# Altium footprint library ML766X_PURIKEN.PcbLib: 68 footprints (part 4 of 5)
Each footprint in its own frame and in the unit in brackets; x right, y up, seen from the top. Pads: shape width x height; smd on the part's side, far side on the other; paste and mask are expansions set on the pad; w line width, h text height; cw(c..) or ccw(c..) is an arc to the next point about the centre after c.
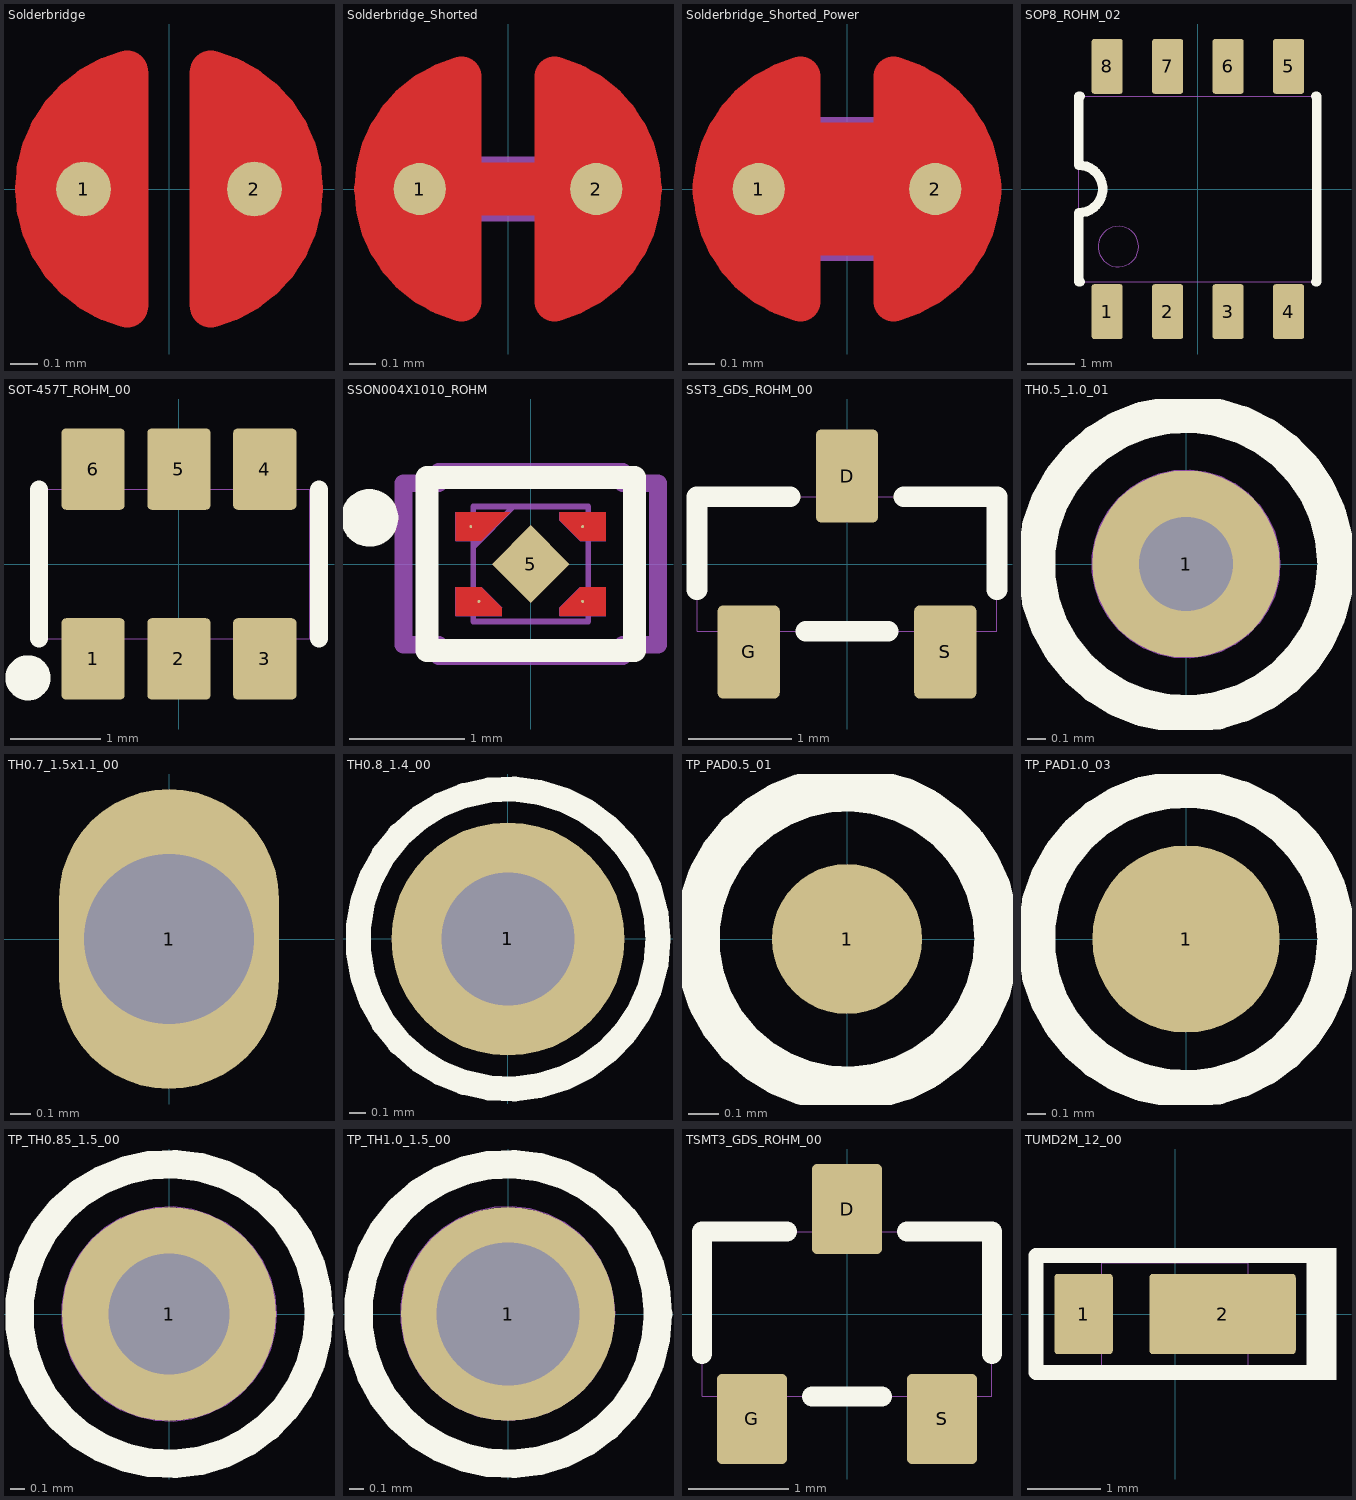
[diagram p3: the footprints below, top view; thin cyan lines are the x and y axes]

## Solderbridge [mm]
height 0.55
pads (2):
  round 0.2 smd paste-10: 1(-0.312,0) 2(0.312,0)
Top Layer:
  region: -0.077,-0.432 -0.152,-0.505 -0.271,-0.467 -0.335,-0.424 -0.409,-0.351 -0.462,-0.292 -0.521,-0.193 -0.549,-0.099 -0.544,0.122 -0.518,0.193 -0.434,0.33 -0.351,0.411 -0.259,0.469 -0.157,0.5 -0.107,0.483 -0.077,0.43
  region: 0.077,0.432 0.152,0.505 0.271,0.467 0.335,0.424 0.409,0.351 0.462,0.292 0.521,0.193 0.549,0.099 0.544,-0.122 0.518,-0.193 0.434,-0.33 0.351,-0.411 0.259,-0.469 0.157,-0.5 0.107,-0.483 0.077,-0.43
  lines w0.152: -0.153,-0.431 cw(c-0.042,0) -0.153,0.431 ; 0.153,-0.431 ccw(c0.042,0) 0.153,0.431
Top Solder:
  circle w0.61: c-0.003,0 r0.279
Top Component Outline:
  lines w0.05: -0.123,-0.459 cw(c-0.042,0) -0.123,0.459 -0.123,-0.459 ; 0.123,-0.459 ccw(c0.042,0) 0.123,0.459 0.123,-0.459

## Solderbridge_Shorted [mm]
height 0.55
pads (2):
  round 0.2 smd paste-10: 1(-0.338,0) 2(0.338,0)
Top Layer:
  region: 0.102,0.432 0.178,0.505 0.296,0.467 0.361,0.424 0.434,0.351 0.488,0.292 0.546,0.193 0.574,0.099 0.569,-0.122 0.544,-0.193 0.46,-0.33 0.376,-0.411 0.284,-0.469 0.183,-0.5 0.132,-0.483 0.102,-0.43
  region: -0.102,-0.432 -0.178,-0.505 -0.296,-0.467 -0.361,-0.424 -0.434,-0.351 -0.488,-0.292 -0.546,-0.193 -0.574,-0.099 -0.569,0.122 -0.544,0.193 -0.46,0.33 -0.376,0.411 -0.284,0.469 -0.183,0.5 -0.132,0.483 -0.102,0.43
  lines w0.152: -0.178,-0.431 cw(c-0.068,0) -0.178,0.431 ; 0.178,-0.431 ccw(c0.068,0) 0.178,0.431
  lines w0.203: -0.338,0 0.338,0
Top Solder:
  circle w0.61: c0.028,0 r0.279
  circle w0.61: c-0.028,0 r0.279
Top Component Outline:
  lines w0.05: -0.148,-0.459 cw(c-0.067,0) -0.148,0.459 -0.148,0.1 0.148,0.1 0.148,0.459 cw(c0.067,0) 0.148,-0.459 0.148,-0.1 -0.148,-0.1 -0.148,-0.459

## Solderbridge_Shorted_Power [mm]
height 2.54
pads (2):
  round 0.2 smd paste-10: 1(-0.338,0) 2(0.338,0)
Top Layer:
  region: -0.102,-0.432 -0.178,-0.505 -0.296,-0.467 -0.361,-0.424 -0.434,-0.351 -0.488,-0.292 -0.546,-0.193 -0.574,-0.099 -0.569,0.122 -0.544,0.193 -0.46,0.33 -0.376,0.411 -0.284,0.469 -0.183,0.5 -0.132,0.483 -0.102,0.43
  region: 0.102,0.432 0.178,0.505 0.296,0.467 0.361,0.424 0.434,0.351 0.488,0.292 0.546,0.193 0.574,0.099 0.569,-0.122 0.544,-0.193 0.46,-0.33 0.376,-0.411 0.284,-0.469 0.183,-0.5 0.132,-0.483 0.102,-0.43
  lines w0.152: -0.178,-0.431 cw(c-0.068,0) -0.178,0.431 ; 0.178,-0.431 ccw(c0.068,0) 0.178,0.431
  lines w0.508: -0.338,0 0.338,0
Top Solder:
  circle w0.61: c0.028,0 r0.279
  circle w0.61: c-0.028,0 r0.279
Top Component Outline:
  lines w0.05: 0.148,-0.25 0.148,-0.459 ccw(c0.067,0) 0.148,0.459 0.148,0.25 -0.148,0.25 -0.148,0.459 ccw(c-0.067,0) -0.148,-0.459 -0.148,-0.25 0.175,-0.25

## SOP8_ROHM_02 [mm]
height 1.75
pads (8):
  rrect15% 0.65x1.15 smd: 1(-1.905,-2.575) 2(-0.635,-2.575) 3(0.635,-2.575) 4(1.905,-2.575) 5(1.905,2.575) 6(0.635,2.575) 7(-0.635,2.575) 8(-1.905,2.575)
Top Overlay:
  lines w0.2: -2.475,-1.95 -2.5,-1.95 -2.5,-0.5 ccw(c-2.5,0) -2.5,0.5 -2.5,1.95 -2.475,1.95 ; 2.475,-1.95 2.5,-1.95 2.5,1.95 2.475,1.95
Top Component Outline:
  circle w0.01: c-1.67,-1.21 r0.426
  lines w0.01: -2.5,-1.95 -2.5,1.95 2.5,1.95 2.5,-1.95 -2.5,-1.95
3D body: height 1.75, standoff 0, extent -2.5,-1.95 2.5,1.95

## SOT-457T_ROHM_00 [mm]
height 1
pads (6):
  rrect14% 0.7x0.9 smd: 1(-0.95,-1.05) 2(0,-1.05) 3(0.95,-1.05) 4(0.95,1.05) 5(0,1.05) 6(-0.95,1.05)
Top Overlay:
  circle w0.3: c-1.67,-1.26 r0.1
  lines w0.2: -1.55,-0.825 -1.55,0.825 ; 1.55,-0.825 1.55,0.825
Top Component Outline:
  lines w0.01: -1.45,-0.825 -1.45,0.825 1.45,0.825 1.45,-0.825 -1.45,-0.825
3D body: height 1, standoff 0, extent -1.45,-0.825 1.45,0.825

## SSON004X1010_ROHM [mm]
height 0.55
pads (5):
  round 0.025 smd paste+0 mask+0.05: 1(-0.521,0.325) 2(-0.45,-0.325) 3(0.45,-0.325) 4(0.45,0.325)
  rect 0.48x0.48 smd rot 45 paste+0 mask+0.05: 5(0,0)
Top Layer:
  region: -0.43,-0.2 -0.25,-0.38 -0.25,-0.45 -0.65,-0.45 -0.65,-0.2
  region: -0.65,0.45 -0.65,0.2 -0.43,0.2 -0.18,0.45
  region: 0.43,-0.2 0.25,-0.38 0.25,-0.45 0.65,-0.45 0.65,-0.2
  region: 0.43,0.2 0.25,0.38 0.25,0.45 0.65,0.45 0.65,0.2
Top Overlay:
  circle w0.3: c-1.4,0.4 r0.1
  lines w0.2: -0.9,-0.75 -0.9,0.75 0.9,0.75 0.9,-0.7 0.9,-0.75 -0.9,-0.75
Top Component Outline:
  lines w0.005: 0.45,-0.2 0.65,-0.2 ; -0.65,0.45 -0.18,0.45 ; -0.65,0.45 -0.65,0.2 -0.43,0.2 -0.18,0.45 ; -0.65,0.45 -0.18,0.45 ; 0.65,-0.2 0.43,-0.2 0.25,-0.38 0.25,-0.45 0.65,-0.45 0.65,-0.2 ; -0.65,-0.45 -0.65,-0.2 -0.43,-0.2 -0.25,-0.38 -0.25,-0.45 -0.65,-0.45 ; 0.25,0.38 0.25,0.45 0.65,0.45 0.65,0.2 0.43,0.2 0.25,0.38
  lines w0.05: -0.5,0.15 -0.15,0.5 ; -0.5,-0.5 -0.5,0.5 0.5,0.5 0.5,-0.5 -0.5,-0.5
Mechanical 15:
  lines w0.152: -1.105,-0.701 -1.105,0.701 -0.8,0.701 -0.8,0.8 0.8,0.8 0.8,0.701 1.105,0.701 1.105,-0.701 0.8,-0.701 0.8,-0.8 -0.8,-0.8 -0.8,-0.701 -1.105,-0.701
3D body "MIC5317-1.5YMT-TZ.stp": height 0.53, standoff -0.02, extent -0.52,-0.5 0.524,0.5

## SST3_GDS_ROHM_00 [mm]
height 1.2
pads (3):
  rrect17% 0.6x0.9 smd: D(0,0.85) G(-0.95,-0.85) S(0.95,-0.85)
Top Overlay:
  lines w0.2: -1.45,-0.25 -1.45,0.65 -0.55,0.65 ; -0.4,-0.65 0.4,-0.65 ; 0.55,0.65 1.45,0.65 1.45,-0.25
Top Component Outline:
  lines w0.01: -1.45,-0.65 -1.45,0.65 1.45,0.65 1.45,-0.65 -1.45,-0.65
3D body: height 1.2, standoff 0, extent -1.45,-0.65 1.45,0.65

## TH0.5_1.0_01 [mm]
pads (1):
  round 1 / inner round 1.524 / far side round 1 hole 0.5: 1(0,0)
Top Overlay:
  circle w0.2: c0,0 r0.8
Top Component Outline:
  circle w0.01: c0,0 r0.5

## TH0.7_1.5x1.1_00 [mm] "1.27ピッチ用"
height 5
pads (1):
  oval 1.1x1.5 hole 0.85 mask-2539.97: 1(0,0)
Top Solder:
  lines w1.16: 0,-0.22 0,0.22
Bottom Solder:
  lines w1.16: 0,-0.22 0,0.22

## TH0.8_1.4_00 [mm]
pads (1):
  round 1.4 hole 0.8 mask+0.05: 1(0,0)
Top Overlay:
  circle w0.15: c0,0 r0.9

## TP_PAD0.5_01 [mm]
pads (1):
  round 0.5 smd: 1(0,0)
Top Overlay:
  circle w0.15: c0,0 r0.5
Top Component Outline:
  circle w0: c0,0 r0.5

## TP_PAD1.0_03 [mm]
height 0.55
pads (1):
  round 1 smd: 1(0,0)
Top Overlay:
  circle w0.2: c0,0 r0.8
Top Component Outline:
  circle w0: c0,0 r0.8

## TP_TH0.85_1.5_00 [mm]
pads (1):
  round 1.5 / inner round 1.524 / far side round 1.5 hole 0.85: 1(0,0)
Top Overlay:
  circle w0.2: c0,0 r1.05
Top Component Outline:
  circle w0.01: c0,0 r0.75

## TP_TH1.0_1.5_00 [mm]
pads (1):
  round 1.5 / inner round 1.524 / far side round 1.5 hole 1: 1(0,0)
Top Overlay:
  circle w0.2: c0,0 r1.05
Top Component Outline:
  circle w0.01: c-0.002,0.004 r0.748

## TSMT3_GDS_ROHM_00 [mm]
height 1
pads (3):
  rrect14% 0.7x0.9 smd: D(0,1.05) G(-0.95,-1.05) S(0.95,-1.05)
Top Overlay:
  lines w0.2: -1.45,-0.4 -1.45,0.825 -0.6,0.825 ; -0.35,-0.825 0.35,-0.825 ; 0.6,0.825 1.45,0.825 1.45,-0.4
Top Component Outline:
  lines w0.01: -1.45,-0.825 -1.45,0.825 1.45,0.825 1.45,-0.825 -1.45,-0.825
3D body: height 1, standoff 0, extent -1.45,-0.825 1.45,0.825

## TUMD2M_12_00 [mm]
height 0.6
pads (2):
  rrect12% 0.8x1.1 smd: 1(-1.25,0)
  rrect9% 2x1.1 smd: 2(0.65,0)
Top Overlay:
  region: 1.8,0.9 2.2,0.9 2.2,-0.9 1.8,-0.9
  lines w0.2: -1.9,-0.8 1.9,-0.8 1.9,0.8 -1.9,0.8 -1.9,-0.8
MASK:
  region: -1.65,-0.55 -1.65,0.55 -0.85,0.55 -0.85,-0.55
  region: -0.35,-0.55 -0.35,0.55 1.65,0.55 1.65,-0.55
Top Component Outline:
  lines w0.01: -1,-0.7 -1,0.7 1,0.7 1,-0.7 -1,-0.7
3D body: height 0.6, standoff 0, extent -1,-0.7 1,0.7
